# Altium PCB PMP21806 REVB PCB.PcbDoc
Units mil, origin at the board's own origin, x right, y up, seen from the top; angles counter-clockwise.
Board outline 1250 x 2200 mil, 2 copper layers (Top Layer, Bottom Layer), stack 62 mil thick; 54 components, 26 nets, 111 pads, 101 vias.
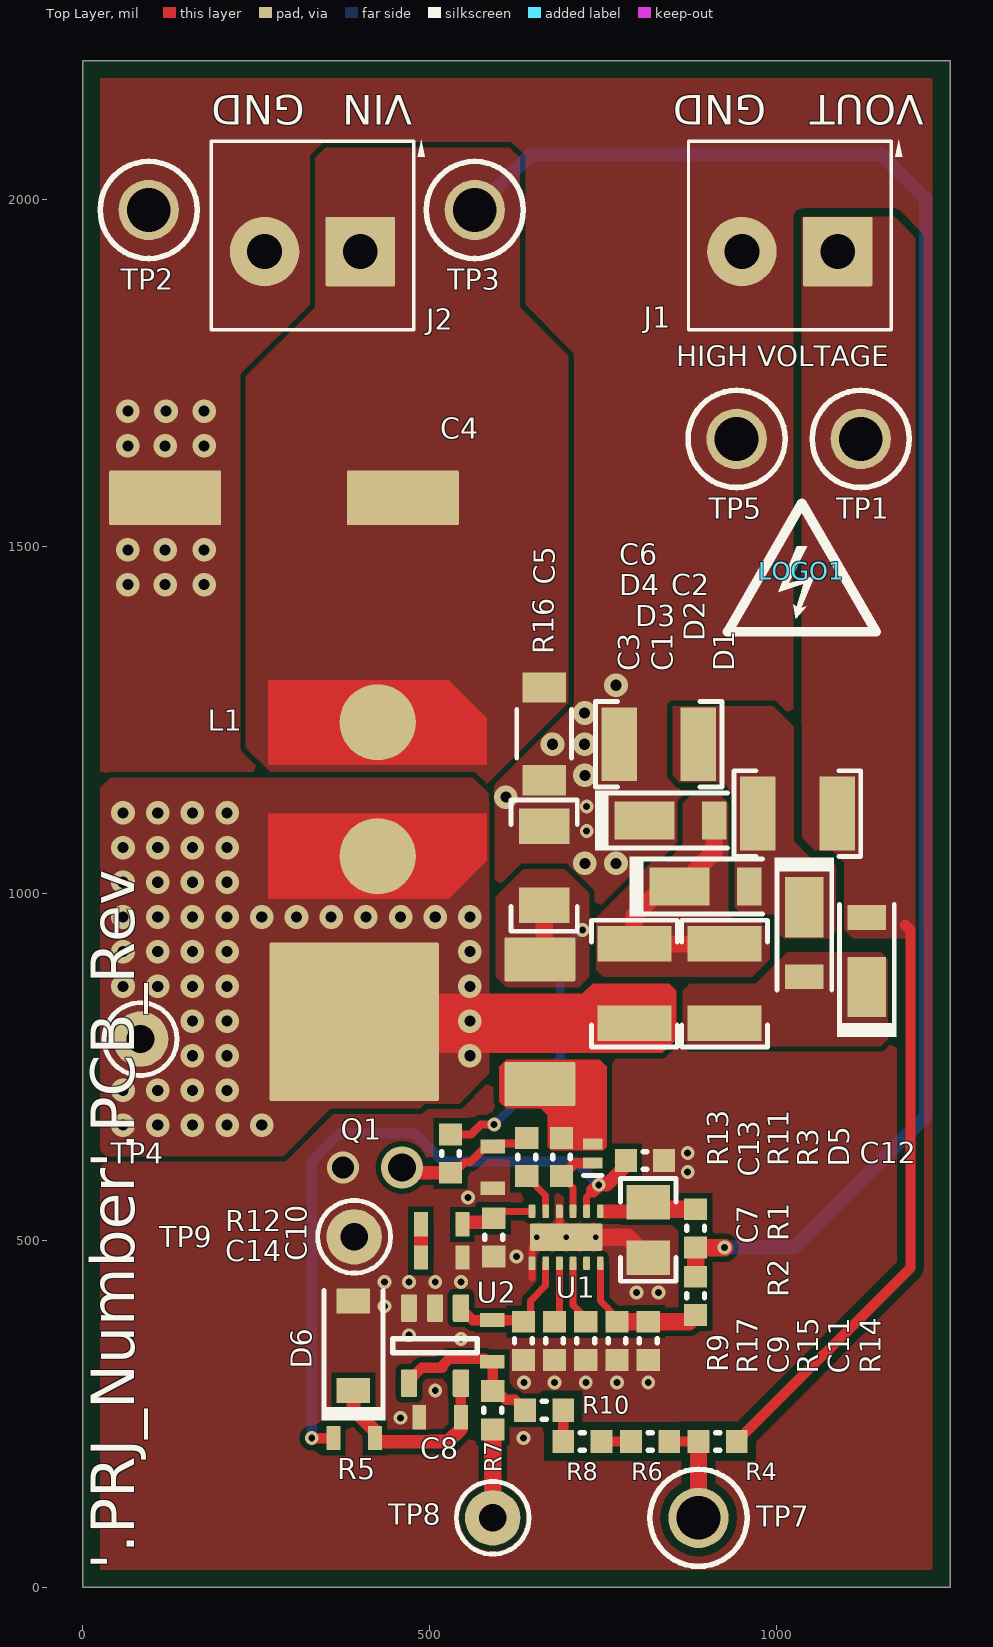
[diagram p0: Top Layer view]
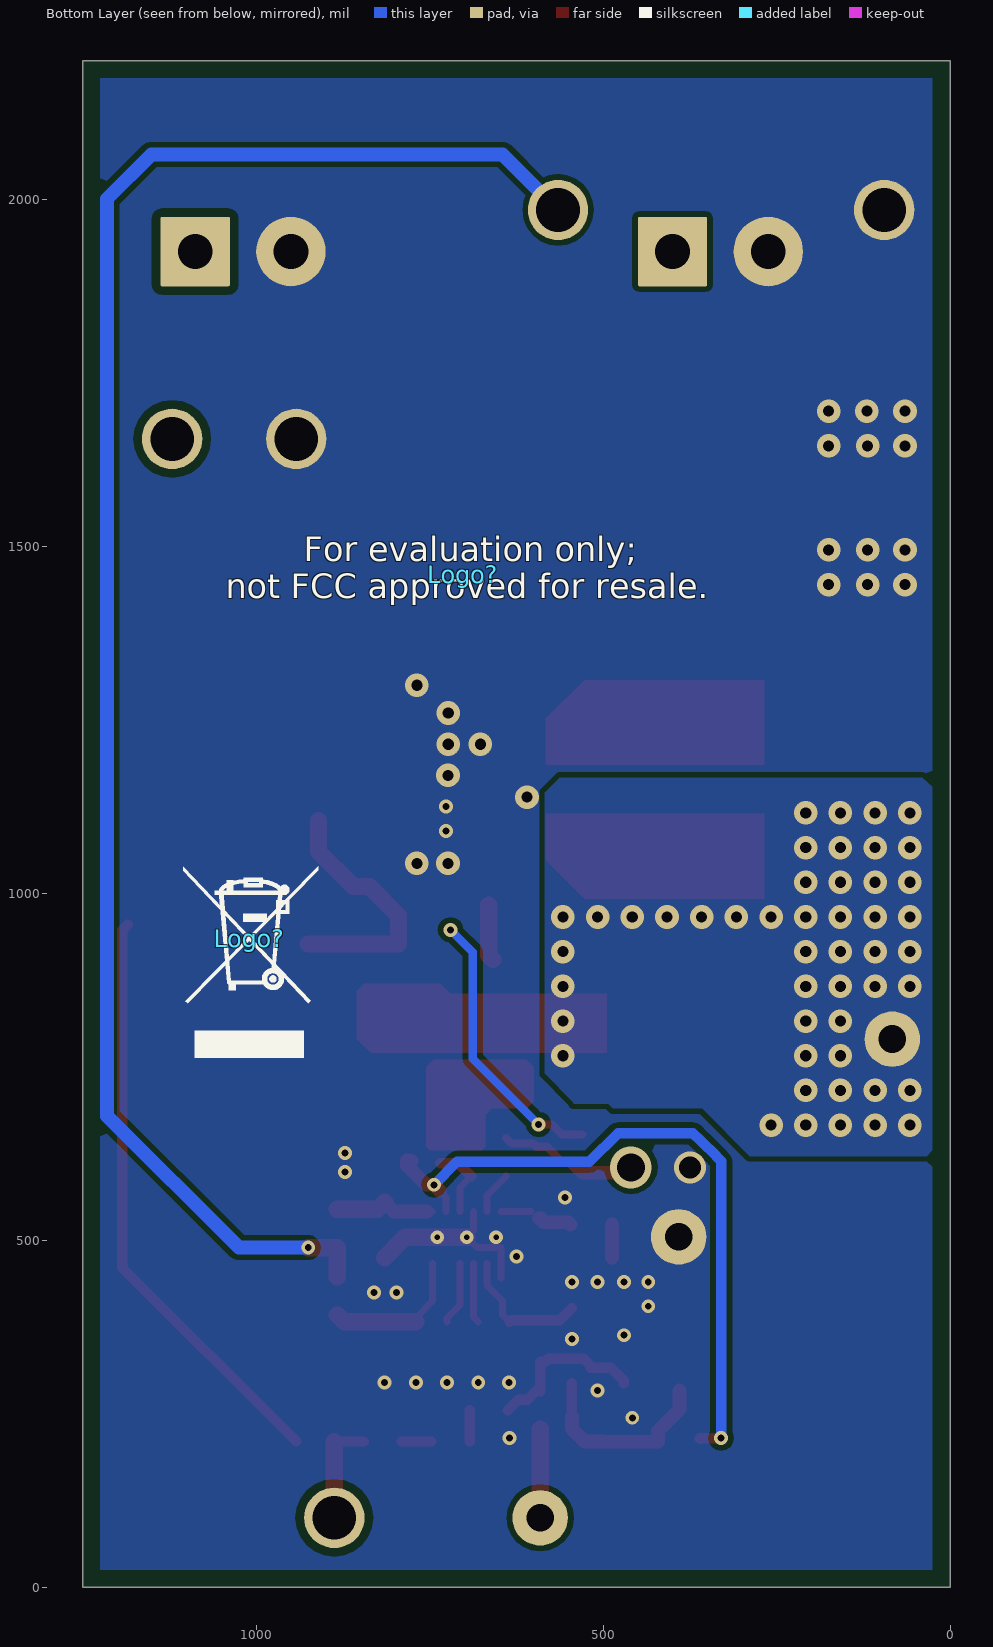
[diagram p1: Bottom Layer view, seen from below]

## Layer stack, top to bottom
Top Solder: solder mask 0.4, Solder Resist, Dk 3.5
Top Layer: signal copper 1.4
Dielectric1: core 59.2, FR-4, Dk 4.8
Bottom Layer: signal copper 1.4
Bottom Solder: solder mask 0.4, Solder Resist, Dk 3.5

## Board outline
0,0 1250,0 1250,2200 0,2200

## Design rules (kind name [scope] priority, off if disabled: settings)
AcuteAngle [All] p1: minimum=4.50000000000000E+0001 checktracksonly=FALSE
AssemblyTestPointUsage [All] p1: valid=2
BoardOutlineClearance BoardOutlineClearance_MountingHoles [OnCopper and InComponentClass('Mounting Holes')] p1: gap=25 ignorepadtopadclearanceinfootprint=FALSE
BoardOutlineClearance BoardOutlineClearance_Poly [OnCopper and InPoly] p2: gap=25 ignorepadtopadclearanceinfootprint=FALSE
BoardOutlineClearance [OnCopper and Not InComponentClass('Logo') and not InComponentClass('FiducialMark') and not InRegion(1000,500,4000,800)] p3: gap=25 ignorepadtopadclearanceinfootprint=FALSE
Clearance Clearance_HV [InNet('Vout') OR InNet('NetR4_2') OR InNet('NetR6_1') OR InNet('NetR8_1')] p1: gap=12 ignorepadtopadclearanceinfootprint=FALSE
Clearance Clearance_Keepouts [((IsTrack Or IsArc) And Not InPoly) And IsFree and IsKeepOut vs ((IsTrack Or IsArc) And Not InPoly) And IsFree and IsKeepOut] p2: gap=0 ignorepadtopadclearanceinfootprint=FALSE
Clearance Clearance_Poly [InPolygon] p3: gap=8 ignorepadtopadclearanceinfootprint=FALSE except(0: Arc-Hole Track-Hole SMDPad-Hole THPad-Hole Via-Hole Fill-Hole Poly-Hole Region-Hole Text-Hole)
Clearance [All] p4: gap=7.87 ignorepadtopadclearanceinfootprint=FALSE except(0: Arc-Hole Track-Hole SMDPad-Hole THPad-Hole Via-Hole Fill-Hole Poly-Hole Region-Hole Text-Hole)
ComponentClearance ComponentClearance_MountingHoles_FiducialMarks [InComponentClass('Mounting Holes') vs InComponentClass('FiducialMark')] p1: gap=50 collisioncheckmode=3 verticalgap=10 showdistances=FALSE
ComponentClearance ComponentClearance_Shunt [InComponentClass('Header') vs InComponentClass('Shunt')] p2: gap=0 collisioncheckmode=3 verticalgap=0 showdistances=FALSE
ComponentClearance ComponentClearance_Logo [InComponentClass('Logo')] p3: gap=50 collisioncheckmode=3 verticalgap=10 showdistances=FALSE
ComponentClearance ComponentClearance_ScrewToNut [(HasFootprint('NY PMS 440 0025 PH')) vs (HasFootprint('Keystone_1902C'))] p4: gap=5 collisioncheckmode=3 verticalgap=10 showdistances=FALSE
ComponentClearance ComponentClearance_MountingHoles [InComponentClass('Mounting Holes')] p5: gap=250 collisioncheckmode=3 verticalgap=100000 showdistances=FALSE
ComponentClearance ComponentClearance_SmallPassives [HasFootprint('0201*') or HasFootprint('0402*') or HasFootprint('0508') or HasFootprint('0603*') or HasFootprint('0612') or HasFootprint('0805*') or HasFootprint('0815*') or HasFootprint('0830*') or HasFootprint('1206*') or HasFootprint('1210*') or HasFootprint('1808*') or HasFootprint('1812*') or HasFootprint('1825*') or HasFootprint('2010*') or HasFootprint('2220*') or HasFootprint('2225*') or HasFootprint('2512*') or HasFootprint('2728*') or HasFootprint('3518*') vs HasFootprint('0201*') or HasFootprint('0402*') or HasFootprint('0508') or HasFootprint('0603*') or HasFootprint('0612') or HasFootprint('0805*') or HasFootprint('0815*') or HasFootprint('0830*') or HasFootprint('1206*') or HasFootprint('1210*') or HasFootprint('1808*') or HasFootprint('1812*') or HasFootprint('1825*') or HasFootprint('2010*') or HasFootprint('2220*') or HasFootprint('2225*') or HasFootprint('2512*') or HasFootprint('2728*') or HasFootprint('3518*')] p6: gap=5 collisioncheckmode=3 verticalgap=10 showdistances=FALSE
ComponentClearance ComponentClearance_THtoSMT [IsThruComponent vs IsSMTComponent] p7: gap=15 collisioncheckmode=3 verticalgap=30 showdistances=FALSE
ComponentClearance ComponentClearance_THtoTH [IsThruComponent vs IsThruComponent] p8: gap=15 collisioncheckmode=3 verticalgap=30 showdistances=FALSE
ComponentClearance [All] p9: gap=5 collisioncheckmode=3 verticalgap=10 showdistances=FALSE
DiffPairsRouting [All] p1: maxlimit=100 minlimit=10 mostfreqgap=10 toplayer_minwidth=15 toplayer_maxwidth=15 toplayer_prefwidth=15 bottomlayer_minwidth=15 bottomlayer_maxwidth=15 bottomlayer_prefwidth=15 maxuncoupledlength=1000
FabricationTestPointUsage TestPointUsage [All] p1: valid=2 allowmultiple=FALSE
FabricationTestpoint Testpoint [All] p1: side=3 testpointundercomponent=TRUE minsize=40 maxsize=100 preferedsize=60 minholesize=0 maxholesize=40 preferedholesize=32 testpointgrid=1 allowsidetop=TRUE allowsidebottom=TRUE usegrid=TRUE gridtolerance=0.01
FanoutControl Fanout_LCC [IsLCC] p1: bgadir=Out bgaviamode=Centered fanoutstyle=Auto fanoutdirection=Alternating viagrid=1 // Fanout_LCC (Default Rule)
FanoutControl Fanout_BGA [IsBGA] p2: bgadir=Out bgaviamode=Centered fanoutstyle=Auto fanoutdirection=Alternating viagrid=1 // Fanout_BGA (Default Rule)
FanoutControl Fanout_Default [All] p4: bgadir=Out bgaviamode=Centered fanoutstyle=Auto fanoutdirection=Alternating viagrid=1 // Fanout_Default (Default Rule)
FanoutControl Fanout_Small [(CompPinCount < 5)] p5: bgadir=Out bgaviamode=Centered fanoutstyle=Auto fanoutdirection=OutThenIn viagrid=1 // Fanout_Small (Default Rule)
HoleSize [All] p1: absolutevalues=TRUE maxlimit=251 minlimit=7.87 maxpercent=80.000 minpercent=20.000
MinimumAnnularRing MinimumAnnularRing_ThermalPadVias [IsVia and InAnyComponent] p1: minimumring=4
MinimumAnnularRing [All] p2: minimumring=4
MinimumSolderMaskSliver MinimumSolderMaskSliver_Logo [InComponentClass('Logo') vs InComponentClass('Logo')] p1: minsoldermaskwidth=0.7
MinimumSolderMaskSliver [All] p2: minsoldermaskwidth=2
PlaneClearance [All] p1: clearance=15
PlaneConnect [All] p1: planeconnectstyle=Direct reliefexpansion=10 reliefentries=4 reliefconductorwidth=10 reliefairgap=10
PolygonConnect [All] p1: connectstyle=Direct reliefconductorwidth=10 reliefentries=4 polygonreliefangle="90 Angle" airgapwidth=10
RoutingVias ThermalPadVias [IsVia and InAnyComponent] p1: holewidth=7.87 width=19.68 viastyle="Through Hole" minholewidth=7.87 minwidth=19.68 maxholewidth=12.99 maxwidth=23.62
RoutingVias [All] p2: holewidth=10 width=20 viastyle="Through Hole" minholewidth=6 minwidth=10 maxholewidth=40 maxwidth=65
SilkToBoardRegionClearance [Not ((IsComment or IsDesignator) And (Hide <> 'False')) and not InRegion(1000,500,4000,800)] p1:
SilkToSilkClearance SilkToSilkClearance_Pb-FreeLogo [(HasFootprint('Pb-Free_Overlay_Medium') OR HasFootprint('Pb-Free_Overlay_Small')) vs (HasFootprint('Pb-Free_Overlay_Medium') OR HasFootprint('Pb-Free_Overlay_Small'))] p1: silktosilkclearance=0
SilkToSilkClearance [All] p2: silktosilkclearance=0
SilkToSolderMaskClearance SilkToComponentPadClearance [IsPad and InAnycomponent] p1: minsilkscreentomaskgap=0 clearancetoexposedcopper=TRUE
SilkToSolderMaskClearance "Silk to Solder Mask Opening" [All] p2: minsilkscreentomaskgap=0 clearancetoexposedcopper=FALSE
SolderMaskExpansion [All] p1: expansion=1.97
Width [All] p1: maxlimit=100 minlimit=6 preferedwidth=10 checkconnectedcopper=TRUE
14 further rules are at their usual default settings.

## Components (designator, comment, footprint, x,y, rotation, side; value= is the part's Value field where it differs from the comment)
C1 "GRM32DR72E104KW01L" 1210_220 925,870 r270 top value=0.1uF
C2 "GRM32DR72E104KW01L" 1210_220 1030,1115 r180 top value=0.1uF
C3 "GRM32DR72E104KW01L" 1210_220 795,870 r90 top value=0.1uF
C4 "EEHZS1H221P" FP-EEHZS1H221P_RADIAL_SMD-MFG 290,1570 r0 top
C5 "CGA5L3X7R1H475K160AE" 1206_190 665,1230 r270 top value=4.7uF
C6 "GRM32DR72E104KW01L" 1210_220 830,1215 r180 top value=0.1uF
C7 "CGA4J3X7R1H105K125AB" 0805_HV 815,515 r270 top value=1uF
C8 "CGJ3E2X7R1C104K080AA" 0603S 514.9,245 r180 top value=0.1uF
C9 "CGA3E2X7R1H104K080AA" 0603L 680,355 r270 top value=0.1uF
C10 "GRM1885C1H100JA01D" 0603L 592.46,504.31 r270 top value=10pF
C11 "GRM1885C1H100JA01D" 0603L 770,355 r270 top value=10pF
C12 "GCM188R71C105KA64J" 0603L 810.31,615 r180 top value=1uF
C13 "GRM188R71H272KA01D" 0603S 590.83,605 r270 top value=2700pF
C14 "UMK107AB7105KA-T" 0603S 517.21,475.22 r0 top value=1uF
D1 "DFLU1200-7" PowerDI123 1130,915 r90 top value=200V
D2 "DFLU1200-7" PowerDI123 1040,929.8 r270 top value=200V
D3 "DFLU1200-7" PowerDI123 910.2,1010 r0 top value=200V
D4 "DFLU1200-7" PowerDI123 860,1105 r0 top value=200V
D5 "BAT54LP-7" X1-DFN1006-2 735,625 r90 top value=30V
D6 "MMSZ4688T1G" SOD-123 390,348.11 r90 top value=4.7V
J1 "ED555/2DS" TERM_BLK_ED555-2DS 1088,1925 r180 top
J2 "ED555/2DS" TERM_BLK_ED555-2DS 400,1925 r180 top
L1 "SRT8045-402ME" FP-SRT8045-402ME_SMT_IND_8MM0_8MM4-MFG 425,1150 r270 top
LOGO1 "DANGER HIGH VOLTAGE" IEC_HighVoltage_Small 1036.3,1465 r0 top
Logo? "WEEE logo" WEEE_Minimum 1010,935 r180 bottom
Logo? "FCC disclaimer" FCC_disclaimer_stacked 702.1,1460 r180 bottom
Q1 "IPD5N25S3430ATMA1" DPAK 525,815 r180 top value=250V
R1 "CRCW060310R0FKEA" 0603L 883.29,517.21 r270 top value=10.0
R2 "CRCW060360K4FKEA" 0603L 883.29,420 r90 top value=60.4k
R3 "CRCW060310R0FKEA" 0603L 690,620 r270 top value=10.0
R4 "CRCW060349R9FKEA" 0603L 915,210.12 r180 top value=49.9
R5 "CRCW06031K00FKEA" 0603S 391.14,215 r180 top value=1.00k
R6 "CRCW0603511KFKEA" 0603L 817.68,210 r0 top value=511k
R7 "CRCW060318K2FKEA" 0603L 590.83,255 r90 top value=18.2k
R8 "CRCW0603511KFKEA" 0603L 720,210 r0 top value=511k
R9 "CRCW060322K6FKEA" 0603S 590,355 r270 top value=22.6k
R10 "CRCW0603511KFKEA" 0603L 665,255 r0 top value=511k
R11 "CRCW06030000Z0EA" 0603L 640,620 r270 top value=0
R12 "ERA-3AEB101V" 0603S 517.25,523.01 r0 top value=100
R13 "CRCW0603100RFKEA" 0603L 530,625 r90 top value=100
R14 "CRCW060320K0FKEA" 0603L 815,355 r90 top value=20.0k
R15 "CRCW060388K7FKEA" 0603L 725,355 r90 top value=88.7k
R16 "CSR1206FK20L0" 1206 665,1040 r270 top value=0.02
R17 "CRCW06036K49FKEA" 0603L 635,355 r90 top value=6.49k
TP1 "5010" Keystone5010 1121.2,1655 r0 top
TP2 "5011" Keystone5011 95,1985 r180 top
TP3 "5010" Keystone5010 565,1985 r180 top
TP4 "5000" Keystone5000 83.31,790 r180 top
TP5 "5011" Keystone5011 942.33,1655 r180 top
TP7 "5013" Keystone5013 887.44,100 r180 top
TP8 "5000" Keystone5000 590.83,100 r180 top
TP9 "5001" Keystone5001 391.14,505 r180 top
U1 "LM5155QDSSTQ1" DSS0012C 696.7,504.31 r270 top
U2 "TLV314QDBVRQ1" DBV0005A_N 507.6,348.11 r270 top

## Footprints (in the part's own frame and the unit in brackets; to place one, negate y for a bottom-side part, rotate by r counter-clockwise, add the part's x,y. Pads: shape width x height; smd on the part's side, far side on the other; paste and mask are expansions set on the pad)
0603L [mm] "0603 from SM-752 data"
  rect 0.8x0.85 smd: 1(-0.7,0) 2(0.7,0)
  silkscreen extent -0.07,-0.33 0.07,0.33, body extent -0.87,-0.47 0.87,0.47, height 1
0603S [mil]
  rect 20x35 smd: 1(-30,0) 2(30,0)
  body extent -34,-19 34,19, height 39
0805_HV [mil] "0805 with 30mil clearance between pads"
  rect 50x63 smd: 1(-40,0) 2(40,0)
  silkscreen extent -74,-40 74,40, body extent -43,-29 43,29, height 57
1206 [mm] "1206 from SM-752 data"
  rect 1.3x1.85 smd: 1(-1.45,0) 2(1.45,0)
  silkscreen extent -2.4,-1.21 2.4,1.21, body extent -1.7,-0.9 1.7,0.9, height 1.35
1206_190 [mm] "1206_190"
  rect 1.1x1.6 smd: 1(-1.7,0) 2(1.7,0)
  silkscreen extent -0.9,-1 0.9,1, body extent -1.75,-0.95 1.75,0.95, height 1.9
1210_220 [mm] "1210"
  rect 1.3x2.7 smd: 1(-1.45,0) 2(1.45,0)
  silkscreen extent -2.32,-1.57 2.32,1.57, body extent -1.7,-1.35 1.7,1.35, height 2.2
DBV0005A_N [mm] "SOT23, 5-Leads, Body 2.9x1.6mm, Pitch 0.95mm, Lead Span 2.8mm, IPC Medium Density"
  rrect17% 1x0.6 smd: 1(-1.375,0.95) 2(-1.375,0) 3(-1.375,-0.95) 4(1.375,-0.95) 5(1.375,0.95)
  silkscreen extent -0.25,-1.55 0.25,1.55, body extent -1.42,-1.46 1.42,1.46, height 1.09
DPAK [mm] "D-PAK, 3-Pads, Body 6.22x6.73mm (max), TO-252AA using nominal STEP model"
  rrect6% 2.6x1.6 smd: 1(-3.4,2.28) 3(-3.4,-2.28)
  rrect2% 6.2x5.8 smd paste-3: 2(3.4,0)
  body extent -3.86,-3.29 5.84,3.29, height 2.48
DSS0012C [mm] "WSON-12"
  rrect40% 0.5x0.25 smd: 1(-0.95,1.25) 2(-0.95,0.75) 3(-0.95,0.25) 4(-0.95,-0.25) 5(-0.95,-0.75) 6(-0.95,-1.25) 7(0.95,-1.25) 8(0.95,-0.75) 9(0.95,-0.25) 10(0.95,0.25) 11(0.95,0.75) 12(0.95,1.25)
  rrect11% 0.95x1.17 on Top Paste: 13(0,0.685) 13(0,-0.685)
  rrect11% 1x2.65 smd paste-0.5: 13(0,0)
  body extent -1,-1.5 1,1.5, height 0.81
FCC_disclaimer_stacked [mil]
FP-EEHZS1H221P_RADIAL_SMD-MFG [mm]
  rrect5% 4.1x2 smd paste+0 mask+0: 1(-4.35,0) 2(4.35,0)
  body extent -6.65,-5.5 6.65,5.5, height 0.25
FP-SRT8045-402ME_SMT_IND_8MM0_8MM4-MFG [mm]
  round 2.79 smd paste+0 mask+0: 1(-2.45,0) 2(2.45,0)
  Top Layer region: 0.9,4 0.9,-4 4,-4 4,2.6 2.6,4
  Top Layer region: -0.9,4 -0.9,-4 -4,-4 -4,2.6 -2.6,4
  body extent -4.25,-4.45 4.25,4.45, height 0.25
IEC_HighVoltage_Small [mil]
  silkscreen extent -107,-88 107,97
Keystone5000 [mil] "For Keystone 500x miniature loop terminals"
  round 80 hole 40: 1(0,0)
  silkscreen extent -52,-52 52,52, body extent -49,-49 49,49, height 182
Keystone5001 [mil] "For Keystone 500x miniature loop terminals"
  round 80 hole 40: 1(0,0)
  silkscreen extent -52,-52 52,52, body extent -49,-49 49,49, height 182
Keystone5010 [mil] "Keystone Multipurpose loops"
  round 87 hole 63: 1(0,0)
  silkscreen extent -70,-70 70,70, body extent -63,-63 63,62, height 319
Keystone5011 [mil] "Keystone Multipurpose loops"
  round 87 hole 63: 1(0,0)
  silkscreen extent -70,-70 70,70, body extent -63,-63 63,62, height 319
Keystone5013 [mil] "Keystone Multipurpose loops"
  round 87 hole 63: 1(0,0)
  silkscreen extent -70,-70 70,70, body extent -63,-63 63,62, height 319
PowerDI123 [mm] "Diodes Inc recommended land pattern, document number DS30628 Rev. 6-2"
  rect 2.2x1.4 smd: 1(-1.275,0)
  rect 0.9x1.4 smd: 2(1.275,0)
  silkscreen extent -3.1,-1.09 1.76,1.09, body extent -2.38,-0.97 1.52,0.96, height 1
SOD-123 [mm] "On Semi recommended land pattern"
  rect 0.915x1.22 smd: 1(-1.637,0) 2(1.637,0)
  silkscreen extent -2.74,-1.17 2.03,1.17, body extent -1.93,-0.9 1.93,0.9, height 1.35
TERM_BLK_ED555-2DS [mil]
  rrect4% 100x100 hole 50: 1(0,0)
  round 100 hole 50: 2(138,0)
  silkscreen extent -93,-161 215,113, body extent -69,-150 207,106, height 323
WEEE_Minimum [mil] "WEEElie bin"
  silkscreen extent -95,-172 99,104
X1-DFN1006-2 [mm] "DIODES, INC"
  rect 0.4x0.7 smd: 1(-0.35,0) 2(0.35,0)
  silkscreen extent -0.8,-0.35 -0.8,0.35, body extent -0.54,-0.34 0.54,0.34, height 0.53

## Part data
C1 C2 C3 C6: library part CMP-0009192-2, "CAP, CERM, 0.1 uF, 250 V, +/- 10%, X7R, 1210", Cap_Case=1210, Manufacturer=MuRata, Supplier Part Number 1=490-3541-1-ND, TempCo=X7R, Tolerance_%=10%, Value1=Unknown, Value2=250V, ValueDisplayed=0.1uF
C4: library part CMP-0087071-1, "220µF 50V Aluminum Polymer Capacitor Radial, Can - SMD 13 mOhm 4000 Hrs @ 125°C", Manufacturer="Panasonic Electronic Components", Tolerance_%=20%
C5: library part CMP-0085349-1, "CAP, CERM, 4.7 µF, 50 V,+/- 10%, X7R, AEC-Q200 Grade 1, 1206", Cap_Case=1206, Manufacturer=TDK, TempCo=X7R, Tolerance_%=10%, Value2=50V, ValueDisplayed=4.7µF
C7: library part CMP-0007976-2, "CAP, CERM, 1 uF, 50 V, +/- 10%, X7R, AEC-Q200 Grade 1, 0805", Cap_Case=0805, Manufacturer=TDK, Supplier Part Number 1=445-6961-1-ND, TempCo=X7R, Tolerance_%=10%, Value1="0.008782 ohm", Value2=50V, ValueDisplayed=1uF
C8: library part CMP-0007106-4, "CAP, CERM, 0.1 uF, 16 V, +/- 10%, X7R, AEC-Q200 Grade 1, 0603", Cap_Case=0603, Manufacturer=TDK, Supplier Part Number 1=445-8136-1-ND, TempCo=X7R, Tolerance_%=10%, Value1=Unknown, Value2=16V, ValueDisplayed=0.1uF
C9: library part CMP-0007078-4, "CAP, CERM, 0.1 uF, 50 V, +/- 10%, X7R, AEC-Q200 Grade 1, 0603", Cap_Case=0603, Manufacturer=TDK, Supplier Part Number 1=445-5666-1-ND, TempCo=X7R, Tolerance_%=10%, Value1="0.0296 ohm", Value2=50V, ValueDisplayed=0.1uF
C10 C11: library part CMP-0007170-4, "CAP, CERM, 10 pF, 50 V, +/- 5%, C0G/NP0, 0603", Cap_Case=0603, Manufacturer=MuRata, Supplier Part Number 1=490-1403-1-ND, TempCo=C0G/NP0, Tolerance_%=5%, Value1=Unknown, Value2=50V, ValueDisplayed=10pF
C12: library part CMP-0079154-1, "CAP, CERM, 1 µF, 16 V,+/- 10%, X7R, AEC-Q200 Grade 1, 0603", Cap_Case=0603, Manufacturer=MuRata, Supplier Part Number 1=490-12657-1-ND, TempCo=X7R, Tolerance_%=10%, Value2=16V, ValueDisplayed=1µF
C13: library part CMP-0007447-4, "CAP, CERM, 2700 pF, 50 V, +/- 10%, X7R, 0603", Cap_Case=0603, Manufacturer=MuRata, Supplier Part Number 1=490-1502-1-ND, TempCo=X7R, Tolerance_%=10%, Value1=Unknown, Value2=50V, ValueDisplayed=2700pF
C14: library part CMP-0007508-5, "CAP, CERM, 1 uF, 50 V, +/- 10%, X7R, 0603", Cap_Case=0603, Manufacturer="Taiyo Yuden", Supplier Part Number 1=587-3247-1-ND, TempCo=X7R, Tolerance_%=10%, Value1=Unknown, Value2=50V, ValueDisplayed=1uF
D1 D2 D3 D4: library part CMP-0077072-2, "Diode, Superfast Rectifier, 200 V, 1 A, AEC-Q101, PowerDI123", Manufacturer="Diodes Inc.", Value1=1A, Value2=0.98V
D5: library part CMP-0076931-2, "Diode, Schottky, 30 V, 0.2 A, 1.00x0.50x0.60mm", Manufacturer="Diodes Inc.", Value1=0.2A, Value2=1V
D6: library part CMP-0005785-3, "Diode, Zener, 4.7 V, 500 mW, SOD-123", Manufacturer="ON Semiconductor", Power_W=500mW, Value1=0.5W
J1 J2: library part CMP-0074913-1, "Terminal Block, 3.5mm Pitch, 2x1, TH", Color=Grey, Current_A=6A, Manufacturer="On-Shore Technology", Supplier Part Number 1=ED1514-ND, Voltage_V=150V
L1: library part CMP-0086514-1, "Shielded Power Inductor 4uH 14.5mOhm 9.9A Surface Mount", Manufacturer=Coilcraft
LOGO1: library part CMP-0074835-1, "IEC 61010-1 High Voltage Warning"
Logo?: library part CMP-0074769-1
Logo?: library part CMP-0074847-1, "FCC_disclaimer"
Q1: library part CMP-0082696-2, "MOSFET, N-CH, 250 V, 5 A, AEC-Q101, DPAK", Alternate Manufacturer=None, Manufacturer="Infineon Technologies", Supplier Part Number 1=IPD5N25S3430ATMA1-ND, Value1="? ohm", Value2="4.7 nC"
R1 R3: library part CMP-0022003-4, "RES, 10.0, 1%, 0.1 W, AEC-Q200 Grade 0, 0603", Manufacturer=Vishay-Dale, Power_W=100mW, Supplier Part Number 1=541-10.0HCT-ND, TempCo="100 ppm/C", Tolerance_%=1%, Value2=0.1W, Value_Code=10R0, ValueDisplayed=10.0
R2: library part CMP-0022532-4, "RES, 60.4 k, 1%, 0.1 W, AEC-Q200 Grade 0, 0603", Manufacturer=Vishay-Dale, Power_W=100mW, Supplier Part Number 1=541-60.4KHCT-ND, TempCo="100 ppm/C", Tolerance_%=1%, Value2=0.1W, Value_Code=60k4, ValueDisplayed=60.4k
R4: library part CMP-0022448-4, "RES, 49.9, 1%, 0.1 W, AEC-Q200 Grade 0, 0603", Manufacturer=Vishay-Dale, Power_W=100mW, Supplier Part Number 1=541-49.9HCT-ND, TempCo="100 ppm/C", Tolerance_%=1%, Value2=0.1W, Value_Code=49R9, ValueDisplayed=49.9
R5: library part CMP-0022109-5, "RES, 1.00 k, 1%, 0.1 W, AEC-Q200 Grade 0, 0603", Manufacturer=Vishay-Dale, Power_W=100mW, Supplier Part Number 1=541-1.00KHCT-ND, TempCo="100 ppm/C", Tolerance_%=1%, Value2=0.1W, Value_Code=1k00, ValueDisplayed=1.00k
R6 R8 R10: library part CMP-0022480-4, "RES, 511 k, 1%, 0.1 W, AEC-Q200 Grade 0, 0603", Manufacturer=Vishay-Dale, Power_W=100mW, Supplier Part Number 1=541-511KHCT-ND, TempCo="100 ppm/C", Tolerance_%=1%, Value2=0.1W, Value_Code=511k
R7: library part CMP-0022097-4, "RES, 18.2 k, 1%, 0.1 W, AEC-Q200 Grade 0, 0603", Manufacturer=Vishay-Dale, Power_W=100mW, Supplier Part Number 1=541-18.2KHCT-ND, TempCo="100 ppm/C", Tolerance_%=1%, Value2=0.1W, Value_Code=18k2, ValueDisplayed=18.2k
R9: library part CMP-0022221-4, "RES, 22.6 k, 1%, 0.1 W, AEC-Q200 Grade 0, 0603", Manufacturer=Vishay-Dale, Power_W=100mW, Supplier Part Number 1=541-22.6KHCT-ND, TempCo="100 ppm/C", Tolerance_%=1%, Value2=0.1W, Value_Code=22k6, ValueDisplayed=22.6k
R11: library part CMP-0025697-4, "RES, 0, 5%, 0.1 W, AEC-Q200 Grade 0, 0603", Manufacturer=Vishay-Dale, Power_W=100mW, Supplier Part Number 1=541-0.0GCT-ND, TempCo="200 ppm/C", Tolerance_%=5%, Value2=0.1W, Value_Code=0000, ValueDisplayed=0
R12: library part CMP-0023361-3, "RES, 100, 0.1%, 0.1 W, AEC-Q200 Grade 0, 0603", Manufacturer=Panasonic, Power_W=100mW, Supplier Part Number 1=P100DBCT-ND, TempCo="25 ppm/C", Tolerance_%=0.1%, Value2=0.1W, Value_Code=100R, ValueDisplayed=100
R13: library part CMP-0021991-4, "RES, 100, 1%, 0.1 W, AEC-Q200 Grade 0, 0603", Manufacturer=Vishay-Dale, Power_W=100mW, Supplier Part Number 1=541-100HCT-ND, TempCo="100 ppm/C", Tolerance_%=1%, Value2=0.1W, Value_Code=100R, ValueDisplayed=100
R14: library part CMP-0022204-4, "RES, 20.0 k, 1%, 0.1 W, AEC-Q200 Grade 0, 0603", Manufacturer=Vishay-Dale, Power_W=100mW, Supplier Part Number 1=541-20.0KHCT-ND, TempCo="100 ppm/C", Tolerance_%=1%, Value2=0.1W, Value_Code=20k0, ValueDisplayed=20.0k
R15: library part CMP-0022632-4, "RES, 88.7 k, 1%, 0.1 W, AEC-Q200 Grade 0, 0603", Manufacturer=Vishay-Dale, Power_W=100mW, Supplier Part Number 1=541-88.7KHCT-ND, TempCo="100 ppm/C", Tolerance_%=1%, Value2=0.1W, Value_Code=88k7, ValueDisplayed=88.7k
R16: library part CMP-0017260-2, "RES, 0.02, 1%, 0.5 W, 1206", Manufacturer="Stackpole Electronics Inc", Power_W=500mW, Supplier Part Number 1=CSR1206FK20L0CT-ND, TempCo="100 ppm/C", Tolerance_%=1%, Value2=0.5W, Value_Code=R020, ValueDisplayed=0.02
R17: library part CMP-0022561-4, "RES, 6.49 k, 1%, 0.1 W, AEC-Q200 Grade 0, 0603", Manufacturer=Vishay-Dale, Power_W=100mW, Supplier Part Number 1=541-6.49KHCT-ND, TempCo="100 ppm/C", Tolerance_%=1%, Value2=0.1W, Value_Code=6k49, ValueDisplayed=6.49k
TP1 TP3: library part CMP-0055147-1, "Test Point, Multipurpose, Red, TH", Color=Red, Manufacturer=Keystone, Supplier Part Number 1=36-5010-ND
TP2 TP5: library part CMP-0055148-1, "Test Point, Multipurpose, Black, TH", Color=Black, Manufacturer=Keystone, Supplier Part Number 1=36-5011-ND
TP4 TP8: library part CMP-0055137-1, "Test Point, Miniature, Red, TH", Color=Red, Manufacturer=Keystone, Supplier Part Number 1=36-5000-ND
TP7: library part CMP-0055150-1, "Test Point, Multipurpose, Orange, TH", Color=Orange, Manufacturer=Keystone, Supplier Part Number 1=36-5013-ND
TP9: library part CMP-0055138-1, "Test Point, Miniature, Black, TH", Color=Black, Manufacturer=Keystone, Supplier Part Number 1=36-5001-ND
U1: library part CMP-0081538-1, "Automotive Grade 2.2-MHz Wide Input Non-synchronous Boost Controller, DSS0012C (WSON-12)", Alternate Manufacturer="Texas Instruments", Alternate PartNumber=LM5155QDSSRQ1
U2: library part CMP-0073534-1, "3-MHz, Low-Power, Internal EMI Filter, RRIO, Operational Amplifier, DBV0005A (SOT-23-5)", Alternate Manufacturer="Texas Instruments", Alternate PartNumber=TLV314QDBVTQ1

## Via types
v1: diameter 34, hole 16, Top Layer to Bottom Layer, 68 vias
v2: diameter 20, hole 10, Top Layer to Bottom Layer, tented both sides, 28 vias
v3: diameter 19.68, hole 7.87, Top Layer to Bottom Layer, 3 vias
v4: diameter 46, hole 32, Top Layer to Bottom Layer, 1 vias
v5: diameter 60, hole 40, Top Layer to Bottom Layer, 1 vias

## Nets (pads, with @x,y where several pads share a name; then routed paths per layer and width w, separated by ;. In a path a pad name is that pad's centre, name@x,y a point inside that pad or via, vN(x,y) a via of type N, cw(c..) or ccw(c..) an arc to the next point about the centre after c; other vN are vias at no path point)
GND: C4.1 C5.2 C6.2 C7.2 C8.2 C9.2 C10.2 C11.2 C12.1 C13.2 C14.2 D4.1 D6.2 J1.2 J2.2 R14.1 R15.1 R16.1 R17.1 TP2.1 TP5.1 TP9.1 U1.4 U1.7 U1.13@696.7,504.31 U2.2 U2.3 | length 271.1
  Top Layer w10: 647.49,445.73 U1.7 647.49,489.63 682.02,489.63 v3(696.7,504.31) 686.86,514.15 U1.4
  Top Layer w25: v3(696.7,504.31) v3(739.02,504.31) 785.69,504.31 C7.2
  other v1: 723.67,1043.16 768.54,1043.16 609.76,1138.75 723.67,1170 677.01,1215 723.27,1215 723.27,1260 768.54,1300 65,1445 118.74,1445 175,1445 65,1495 118.74,1495 175,1495 65,1645 118.74,1645 175,1645 65,1695 120,1695 175,1695
  other v2: 635,215 458,244.17 508,283.64 635.68,295 680,295 725,295 770,295 815,295 545,357.95 469.92,363.25 435,405 798,425 830,425 435,440 470,440 508,440 545,440 625,476.75 555,561.69 871.85,598.35 871.85,625.83 726.28,1090 726.28,1125
  other v3: 654.38,504.31
  other v4: 375,605
NetC1_1: C1.1 C3.2 D3.1 D4.2 | length 369.1
  Top Layer w25: D4.2 910.2,1060.2 D3.1 837.09,1010 795,967.91 C3.2 C1.1
NetC1_2: C1.2 D1.1 D2.2
NetC2_2: C2.2 C6.1 D2.1 D3.2
NetC3_1: C3.1 L1.2 Q1.2 TP4.1
  other v1: 58,666 108,666 158,666 208,666 258,666 58,716 108,716 158,716 208,716 158,766 208,766 558,766 158,816 208,816 558,816 58,866 108,866 158,866 208,866 558,866 58,916 108,916 158,916 208,916 558,916 58,966 108,966 158,966 208,966 258,966 308,966 358,966 408,966 458,966 508,966 558,966 58,1016 108,1016 158,1016 208,1016 58,1066 108,1066 158,1066 208,1066 58,1116 108,1116 158,1116 208,1116
NetC4_2: C4.2 C5.1 J2.1 L1.1 R1.2 R2.2 TP3.1 | length 2483.9
  Top Layer w25: R2.2 R1.2 883.53,489.41 v2(925,489.41)
  Bottom Layer w20: TP3.1 645,2065 1151.16,2065 1215,2001.16 1215,679.41 1025,489.41 v2(925,489.41)
NetC7_1: C7.1 R1.1 U1.1 | length 147.1
  Top Layer w10: U1.1 753.8,541.71
  Top Layer w20: 753.8,541.71 801.72,541.71 C7.1
  Top Layer w25: C7.1 825.23,544.77 R1.1
NetC8_1: C8.1 D6.1 R5.1 U2.5 | length 284.3
  Top Layer w15: C8.1@545,245.1 U2.5
  Top Layer w20: D6.1 390,256.46 421.14,225.31 R5.1 421.14,209.63 502.31,209.63 502.68,210 526.63,210 545,228.37 545,245.1 C8.1
NetC9_1: C9.1 U1.9 | length 87.2
  Top Layer w10: C9.1 686.86,389.42 U1.9
NetC10_1: C10.1 R12.2 U1.6 | length 93
  Top Layer w10: C10.1@604.27,541.71 U1.6
  Top Layer w20: R12.2 550.2,525.97 585,525.97 589.38,530.35 589.38,531.87 C10.1
NetC11_1: C11.1 R2.1 R14.2 U1.12 | length 211.7
  Top Layer w10: U1.12 745.91,412.33 770,388.25 C11.1
  Top Layer w25: C11.1 R14.2 873.4,382.56 R2.1
NetC12_2: C12.2 R5.2 U1.2 | length 1004.7
  Top Layer w10: U1.2 726.23,562.59 735.6,571.96
  Top Layer w15: v2(330,215) 358.86,215 360,213.86 R5.2
  Top Layer w20: 735.6,571.96 v2(743.64,580) 754.69,580 C12.2@782.75,608.07 ; C12.2@776.34,614.48 C12.2@782.75,608.07 ; C12.2 C12.2@782.75,608.07
  Bottom Layer w15: v2(330,215) 330,613.7 336.63,620.33 336.63,620.89 359.11,643.37 359.67,643.37 370.75,654.45 478.37,654.45 519.89,612.93 710.71,612.93 v2(743.64,580)
NetC13_1: C13.1 R11.1 R13.1 | length 203.9
  Top Layer w12: R13.1 535.28,597.44 550.77,612.93 559.07,612.93 581.14,635 C13.1 596.22,635 600.65,639.43 631.87,639.43 R11.1
  Top Layer w20: v5(460,605) 467.56,597.44 R13.1
NetC14_1: C14.1 R12.1 | length 47.8
  Top Layer w20: C14.1 487.25,475.27 R12.1
NetD5_1: D5.1 R3.2 U1.3 | length 110.4
  Top Layer w10: R3.2 706.54,575.9 U1.3
  Top Layer w15: R3.2 708.78,611.22 D5.1
NetD5_2: D5.2 Q1.1 R3.1 | length 48.6
  Top Layer w10: R3.1 726.22,647.56 D5.2
NetQ1_3: Q1.3 R13.2 R16.2 | length 483
  Top Layer w12: R13.2 559.3,652.56 573.77,667.02 v2(592.98,667.02)
  Top Layer w25: Q1.3 665,910.91 R16.2
  Bottom Layer w12: v2(592.98,667.02) 605.95,680 606.44,680 688.13,761.69 688.13,915.61 v2(720,947.48)
NetR4_2: R4.2 R6.2 TP7.1 | length 152.4
  Top Layer w15: R6.2 887.32,210 R4.2
  Top Layer w25: TP7.1 R4.2
NetR6_1: R6.1 R8.2 | length 42.6
  Top Layer w15: R8.2 R6.1
NetR7_1: R7.1 TP8.1 | length 127.6
  Top Layer w25: R7.1 TP8.1 TP8.1@590.94,99.88
NetR7_2: R7.2 R9.2 R10.1 U2.4 | length 240.5
  Top Layer w15: U2.4 470.2,297.95 488.73,316.48 517.82,316.48 517.82,318.85 528,329.04 579.43,329.04 583.46,325 R9.2 590.83,324.17 R7.2 596.97,282.56 609.53,270 622.44,270 R10.1
NetR8_1: R8.1 R10.2 | length 45
  Top Layer w15: R8.1 692.56,210.12 R10.2
NetR9_1: R9.1 R17.2 U1.8 U2.1 | length 195.8
  Top Layer w10: R17.2 645,392.56 645,412.48 667.17,434.65 U1.8
  Top Layer w15: U2.1 562.24,385 R9.1 632.56,385 R17.2
NetR11_2: R11.2 U1.5 | length 62
  Top Layer w10: R11.2 640,591.75 667.17,564.58 U1.5
NetR15_2: R15.2 U1.10 | length 92
  Top Layer w10: U1.10 706.54,406.7 725,388.25 R15.2
Vout: C2.1 D1.2 J1.1 R4.1 TP1.1 | length 851.9
  Top Layer w15: R4.1 1193,460.56 1193,947 1185,955
pads on no net: U1.11 U1.13@669.73,504.31 U1.13@723.67,504.31

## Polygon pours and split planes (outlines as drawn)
NetC3_1 on Top Layer "TOP_LAYER_NETC3_1_P043" (solid, remove dead copper, pour order 43): 562.24,1166.88 584.12,1145 585.95,1145 585.95,740.42 542.41,696.88 492.91,696.88 486.05,690.02 357.49,690.02 288.65,621.19 33.81,621.19 0,655 0,1126.88 40,1166.88
NetC3_1 on Top Layer "TOP_LAYER_NETC3_1_P053" (solid, remove dead copper, pour order 53): 95,775
Vout on Top Layer "TOP_LAYER_VOUT_P048" (solid, remove dead copper, pour order 48): 1110,935 1199.99,935 1200,935.01 1200,1945 1170,1975 1036.3,1975 1036.3,1081 1055.45,1061.85 1080,1061.85 1097.23,1044.62 1097.23,947.77
no net on Top Layer "TOP_LAYER_NONET_P052" (solid, remove dead copper, pour order 52): 920,1500
Vout on Top Layer "TOP_LAYER_VOUT_P051" (solid, remove dead copper, pour order 51): 1215,973.07
GND on Top Layer "TOP_LAYER_GND_P049" (solid, remove dead copper, pour order 49): 0,0 0,2200 1250,2200 1250,0
NetQ1_3 on Top Layer "TOP_LAYER_NETQ1_3_P035" (solid, remove dead copper, pour order 35): 635,1035 595,995 595,880 610,865 715,865 730,880 730,1000 695,1035
NetC4_2 on Top Layer "TOP_LAYER_NETC4_2_P047" (solid, remove dead copper, pour order 47): 310,1135 235,1210 235,1745 335,1845 335,2060 350,2075 615,2075 630,2060 630,1845 700,1775 700,1275 560,1135
NetC1_1 on Top Layer "TOP_LAYER_NETC1_1_P041" (solid, remove dead copper, pour order 41): 740,890 750,880 965,880 990,905 990,944.99 975,960 940,960 930,970 930,1130 920,1140 875,1140 865,1130 865,1070 840,1045 820,1045 740,965
NetC2_2 on Top Layer "TOP_LAYER_NETC2_2_P039" (solid, remove dead copper, pour order 39): 850,1270 850,1170 860,1160 925,1160 940,1135 940,980 950,970 995,970 1005,960 1005,940 1010,935 1075,935 1085,945 1085,1040 1075,1050 1050,1050 1025,1075 1025,1240 995,1270
NetC1_2 on Top Layer "TOP_LAYER_NETC1_2_P037" (solid, remove dead copper, pour order 37): 875,870 865,860 865,790 875,780 1150,780 1160,790 1160,905 1150,915 1015,915 970,870
NetC3_1 on Bottom Layer "BOTTOM_LAYER_NETC3_1_P045" (solid, remove dead copper, pour order 45): 40,1166.88 562.24,1166.88 584.27,1144.85 584.27,740.42 542.41,698.55 542.41,696.88 492.91,696.88 486.05,690.02 357.49,690.02 288.65,621.19 33.81,621.19 0,655 0,1130
GND on Bottom Layer "BOTTOM_LAYER_GND_P050" (solid, remove dead copper, pour order 50): 0,0 0,2200 1250,2200 1250,0

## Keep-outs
Keep-Out Layer:
  text ".Layer_Name" at 577,-858.49 h60

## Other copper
Top Layer:
  region net NetD5_2: 670,635 675,630 750,630 755,635 755,750 745,760 610,760 600,750 600,700 610,690 660,690 670,680
  region net NetC3_1: 845,870 855,860 855,790 835,770 495,770 495,855 720,855 735,870
  region: 800,865
  region: 20,1050
  region: 747.6,860
  region: 930,1105
  text ".Layer_Name" at 577,-858.49 h60
Bottom Layer:
  text ".Layer_Name" at 577,-858.49 h60

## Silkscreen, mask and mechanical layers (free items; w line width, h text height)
Top Overlay:
  text "GND" at 320,2165 h72.83 r180
  text "VIN" at 475,2165 h72.83 r180
  text "GND" at 985,2165 h72.83 r180
  text "VOUT" at 1212.24,2165 h72.83 r180
  text "HIGH VOLTAGE" at 855,1750 h50
  text "'.PRJ_Number'.PCB_Rev" at 95,25.49 h108.27 r90
  text ".Layer_Name" at 577,-858.49 h60
Bottom Overlay:
  text ".Layer_Name" at 577,-858.49 h60
Top Paste:
  text ".Layer_Name" at 577,-858.49 h60
Bottom Paste:
  text ".Layer_Name" at 577,-858.49 h60
Top Solder:
  text ".Layer_Name" at 577,-858.49 h60
  text ".Layer_Name" at 577,-858.49 h60
Bottom Solder:
  text ".Layer_Name" at 577,-858.49 h60
Drill Guide:
  text ".Layer_Name" at 577,-858.49 h60
M1 Board Outline:
  lines w10: 0,0 0,2200 ; 0,0 1250,0 ; 0,0 1250,0 ; 0,0 0,2200 ; 0,2200 1250,2200 ; 0,2200 1250,2200 ; 1250,0 1250,2200 ; 1250,0 1250,2200
  text ".Layer_Name" at 577,-858.49 h60
M2 Board Dimensions:
  rectangle: 0,-275 125,-150
  rectangle: 125,-400 500,-275
  lines w7: 0,-275 1000,-275 ; 125,-400 125,-150 ; 250,-400 250,-150 ; 500,-400 500,-150 ; 750,-400 750,-150 ; 0,-400 1000,-400 1000,-150 0,-150 0,-400
  text ".Layer_Name" at 577,-858.49 h60
M3 3D STEP Top:
  text ".Layer_Name" at 577,-858.49 h60
M4 3D STEP Bottom:
  text ".Layer_Name" at 577,-858.49 h60
M5 Assembly Top:
  lines w10: -292,-930.17 6308,-930.17 ; -292,-726.83 6310,-726.83 ; -292,-523.5 -292,-1133.5 3713,-1133.5 6310,-1133.5 6310,-523.5 -291.5,-523.5 -291.5,-1133.5 1284,-1133.5 ; 2173,-1133.5 2173,-523.5 ; 3440,-726.83 3440,-523.5 ; 4280,-726.83 4280,-523.5 ; 4902,-1140 4902,-937.17
  text "PMP21806B" at 105,35 h110 r90
  text "COMPONENTS MARKED 'DNP' SHOULD NOT BE POPULATED." at 1153.5,-318.5 h60
  text "ASSEMBLY VARIANT:" at 1153,-434 h60
  text ".VariantName" at 2189,-434 h60
  text "PCB VIEWED FROM TOP SIDE" at -228.5,-655.67 h60
  text "BOARD #:" at 2248,-655.67 h60
  text ".PRJ_Number" at 2793.5,-655.67 h60
  text "REV:" at 3638,-655.67 h60
  text ".PCB_Rev" at 3929.5,-655.67 h60
  text "SVN REV:" at 4476,-655.67 h60
  text ".VersionControl_RevNumber" at 4982,-655.67 h60
  text "TID #:" at 2248,-859 h60
  text ".TID" at 2793.5,-859 h60
  text "PLOT NAME =" at -228.5,-1064.34 h60
  text ".plot_File_Name" at 577,-1064.34 h60
  text "GENERATED    :" at 2250,-1064.34 h60
  text ".Print_Date" at 3119.5,-1064.34 h60
  text ".Print_Time" at 3848.5,-1064.34 h60
  text "TEXAS INSTRUMENTS" at 5113,-1064.34 h60
M6 Assembly Bottom:
  lines w10: -292.5,-727.33 6309.5,-727.33 ; -290.5,-930.67 6309.5,-930.67 ; 1115.5,-1140.5 1115.5,-937.67 ; 1737.5,-727.33 1737.5,-524 ; 2577.5,-727.33 2577.5,-524 ; 3844.5,-1134 3844.5,-524 ; 4733.5,-1134 6309,-1134 6309,-524 -292.5,-524 -292.5,-1134 2304.5,-1134 6309.5,-1134 6309.5,-524
  text "COMPONENTS MARKED 'DNP' SHOULD NOT BE POPULATED." at 6102,-318 h60
  text ".VariantName" at 5058,-434 h60
  text "ASSEMBLY VARIANT:" at 6097,-434 h60
  text ".VersionControl_RevNumber" at 1035.5,-656.17 h60
  text "SVN REV:" at 1541.5,-656.17 h60
  text ".PCB_Rev" at 2088,-656.17 h60
  text "REV:" at 2379.5,-656.17 h60
  text ".PRJ_Number" at 3224,-656.17 h60
  text "BOARD #:" at 3769.5,-656.17 h60
  text "PCB VIEWED FROM BOTTOM SIDE" at 6246,-656.17 h60
  text ".TID" at 3224,-859.5 h60
  text "TID #:" at 3769.5,-859.5 h60
  text "TEXAS INSTRUMENTS" at 904.5,-1064.84 h60
  text ".Print_Time" at 2169,-1064.84 h60
  text ".Print_Date" at 2898,-1064.84 h60
  text "GENERATED    :" at 3767.5,-1064.84 h60
  text ".plot_File_Name" at 5440.5,-1064.84 h60
  text "PLOT NAME =" at 6246,-1064.84 h60
M9 Title Sheet:
  drawing of 57 lines, arcs and shapes, not listed
  text "1" at 739.84,8036.5 h70
  text "2" at 3235.5,8036.5 h70
  text "3" at 5724.84,8036.5 h70
  text "4" at 8231.51,8036.5 h70
  text "5" at 10730.5,8036.5 h70
  text "6" at 13235.5,8036.5 h70
  text "A" at -416.5,6893.5 h70
  text "A" at 14383.5,6893.5 h70
  text "B" at -416.5,4513.5 h70
  text "B" at 14383.5,4513.5 h70
  text "C" at -416.5,2138.5 h70
  text "C" at 14383.5,2138.5 h70
  text "PROJECT TITLE:" at 11343.5,277.5 h45
  text ".PRJ_Title" at 11393.5,144.17 h70
  text "DESIGNED FOR:" at 11343.5,-23.5 h45
  text ".PRJ_Customer" at 11393.5,-163.5 h70
  text "D" at -416.5,-231.5 h70
  text "D" at 14383.5,-231.5 h70
  text "FILE NAME:" at 11343.5,-323.5 h45
  text ".PCB_File_Name_No_Path" at 11393.5,-443.5 h70
  text "Texas Instruments (TI) and/or its licensors do not warrant the accuracy or completeness of this specification" at 6374,-605.34 h45
  text "ENGINEER:" at 11343.5,-613.5 h45
  text "LAYOUT BY:" at 12848.5,-613.5 h45
  text "or any information contained therein. TI and/or its licensors do not warrant that this design will meet" at 6329.01,-718 h45
  text ".PRJ_Engineer" at 11393.5,-768.49 h70
  text ".PCB_Layout" at 12899,-768.49 h70
  text "the specifications, will be suitable for your application or fit for any particular purpose, or will operate in" at 6329.01,-830.67 h45
  text ".Layer_Name" at 577,-858.49 h60
  text "ALTIUM DESIGNER VERSION:" at 12848.5,-923.5 h45
  text "an implementation. TI and/or its licensors do not warrant that the design is production worthy. You should" at 6329.01,-943.33 h45
  text "completely validate and test your design implementation to confirm the system functionality for your application." at 6374,-1056 h45
  text ".print_Scale" at 11393.5,-1056.83 h70
  text ".Application_BuildNumber" at 12899,-1056.83 h70
  text "1" at 739.84,-1263.5 h70
  text "2" at 3235.5,-1263.5 h70
  text "3" at 5724.84,-1263.5 h70
  text "4" at 8231.51,-1263.5 h70
  text "5" at 10730.5,-1263.5 h70
  text "6" at 13235.5,-1263.5 h70
M10 Fab Notes:
  drawing of 189 lines, arcs and shapes, not listed
  text "DESIGN INFORMATION" at 12382.02,6356.17 h60
  text "MIN. TRACK WIDTH:" at 11737.46,6224.05 h60
  text "8" at 12833.7,6224.05 h60
  text "MIL" at 12988.46,6224.05 h60
  text "MIN. CLEARANCE:" at 11737.46,6099.92 h60
  text "0.2" at 12773.7,6099.93 h60
  text "mm" at 12988.46,6099.92 h60
  text "MIN. VIA PAD SIZE:" at 11737.46,5975.8 h60
  text "24" at 12803.71,5975.8 h60
  text "MIL" at 12988.46,5975.8 h60
  text "0.05mm (2MIL)" at 12432.46,5845.9 h60
  text "MINIMUM ANNULAR RING" at 11408.23,5837.67 h60
  text "EXTERNAL" at 13140.46,5837.67 h60
  text "PER" at 11608.23,5727.55 h60
  text "IPC-D-275 CLASS 2 LEVEL C" at 11828.23,5727.54 h60
  text "MIL, HOLES" at 13316.46,5627.07 h60
  text "+/-" at 12924,5618.48 h60
  text "+/-" at 13778,5618.48 h60
  text "REGISTRATION TOLERANCES:" at 11408.23,5617.42 h60
  text "METAL" at 12608,5617.42 h60
  text "5" at 13184.2,5617.42 h60
  text "3" at 14017.2,5617.42 h60
  text "MIL" at 14133.46,5617.42 h60
  text "HOLE SIZE TOLERANCE (UNLESS OTHERWISE SPECIFIED):" at 11408.23,5519.1 h60
  text "+/-" at 13778,5516.23 h60
  text "3" at 14017.2,5515.17 h60
  text "MIL" at 14133.46,5515.17 h60
  text "MATERIAL:" at 11333.46,5377.52 h60
  text "FR-4 High Tg" at 12319.9,5249 h60
  text "X" at 12175.46,5241.01 h60
  text "FR-408" at 11754.46,5236.49 h60
  text "OTHER" at 13242.46,5236.49 h60
  text "62 MIL (1.6mm) +/-10%" at 12074.56,5093.46 h60
  text "X" at 11954.46,5091.01 h60
  text "THICKNESS:" at 11408.23,5085.24 h60
  text "OTHER" at 13359.46,5085.24 h60
  text "TOLERANCE:" at 11408.23,4946.92 h60
  text "X" at 12256.46,4946.92 h60
  text "ANSI IPC-6012 TYPE 3 CLASS 2" at 12434.48,4946.92 h60
  text "OTHER +/-" at 12434.46,4802.73 h60
  text "BOW & TWIST:" at 11408.23,4657.54 h60
  text "X" at 12256.46,4657.54 h60
  text "ANSI IPC-6012 TYPE 3 CLASS 2" at 12434.48,4657.54 h60
  text "OTHER +/-" at 12434.46,4510.85 h60
  text "DRILLING:" at 11333.46,4380.23 h60
  text "NC_DRILL FILES" at 13094.46,4275.04 h60
  text "REFERENCE:" at 11408.23,4271.1 h60
  text "X" at 12065.46,4271.01 h60
  text "AS SHOWN" at 12243.46,4271.1 h60
  text "X" at 12966.46,4271.1 h60
  text "OTHER" at 13392.46,4128.85 h60
  text "PTH COPPER THICKNESS:" at 11407.91,4125.32 h60
  text "X" at 12547.14,4125.32 h60
  text "20-30 um" at 12675.14,4125.32 h60
  text "BOARD FINISH:" at 11333.46,3977.73 h60
  text "SILKSCREEN:" at 11488.68,3867.6 h60
  text "X" at 12446.46,3867.6 h60
  text "TOP" at 12563.46,3867.6 h60
  text "X" at 12956.46,3867.6 h60
  text "BOTTOM" at 13074.46,3867.6 h60
  text "SILKSCREEN COLOR:" at 11488.68,3712.41 h60
  text "X" at 12445.46,3712.41 h60
  text "WHITE" at 12563.46,3712.41 h60
  text "OTHER" at 13074.46,3712.41 h60
  text "X" at 12576.46,3568.96 h60
  text "GREEN" at 12694.46,3568.96 h60
  text "OTHER" at 13312.46,3568.96 h60
  text "SOLDER RESIST COLOR:" at 11488.68,3562.1 h60
  text "X" at 12576.46,3414.71 h60
  text "MATTE" at 12694.46,3414.71 h60
  text "SEMI-GLOSS" at 13312,3414.07 h60
  text "IMMERSION GOLD (ENIG)" at 12394.46,3241.94 h60
  text "ENEPIG" at 13732,3234.72 h60
  text "SURFACE FINISH:" at 11333.46,3233.72 h60
  text "X" at 12216.46,3233.72 h60
  text "IMM. TIN/SILVER OR EQUIV" at 11663,3096.4 h60
  text "OTHER" at 13094.46,3092.47 h60
  text "ARRAY/PANEL:" at 11333.46,2937.09 h60
  text "CUT AND TRIM PER M1 BOARD OUTLINE" at 12394.46,2928.87 h60
  text "N.C. ROUTE" at 12394.46,2792.9 h60
  text "X" at 13082.46,2792.9 h60
  text "V. SCORE" at 13260.46,2792.9 h60
  text "CERTIFICATION:" at 11333.46,2663.77 h60
  text "MATERIALS AND WORKMANSHIP FOR ALL PCBS" at 12058.46,2663.77 h60
  text "TO MEET OR EXCEED THE REQUIREMENTS OF:" at 12058.46,2569.71 h60
  text "X" at 11695.97,2441.08 h60
  text "ANSI IPC-A-600F CLASS ->" at 11823.96,2441.08 h60
  text "X" at 13471.97,2441.08 h60
  text "2" at 13581.96,2441.08 h60
  text "1" at 13266.96,2439.58 h60
  text "3" at 13935.96,2439.58 h60
  text "X" at 12507.97,2293.39 h60
  text "RoHS" at 12635.96,2293.39 h60
  text "OTHER" at 13280.36,2293.39 h60
  text "PER ORDER" at 13677.42,2293.39 h60
  text "ALL BOARDS MUST MEET OR EXCEED UL94-V0 REQUIREMENTS." at 11361,2139.57 h60
  text "PCB MUST BEAR THE UL94V-0 UL REGISTERED MATERIAL ID NUMBER" at 11361,2023.5 h60
  text "ADDITIONAL REQUIREMENTS:" at 11333.46,1854.08 h60
  text "MICROSECTION:" at 11408.23,1746.95 h60
  text "YES" at 12313.96,1746.95 h60
  text "REQUIRED" at 13175.46,1602.62 h60
  text "BARE BOARD ELEC. TEST:" at 11408.23,1599.76 h60
  text "NONE" at 12713.96,1599.76 h60
  text "X" at 13057.46,1599.76 h60
  text "PER ORDER" at 13767.46,1599.76 h60
  text "XX MIL VIAS REQUIRE NON-CONDUCTIVE FILL AND PLANARIZE" at 11576.38,1394.82 h59
  text "XX MIL VIAS REQUIRE CONDUCTIVE FILL AND PLANARIZE" at 11584.38,1290.84 h60
  text "OUTER XX MIL VIAS REQUIRE 50 OHM SINGLE-ENDED IMPEDANCE" at 11583.39,1127.46 h58
  text "LAYER 2 & 3 (INNER LAYERS) XX MIL WIDE, XX MIL SPACE / TRACES REQUIRE 100 OHM DIFFERENTIAL IMPEDANCE" at 11575.39,891.74 h60
  text ".Layer_Name" at 577,-858.49 h60
M11 Gerber Information:
  lines w10: -292,-930.17 6308,-930.17 ; -292,-726.83 6310,-726.83 ; -292,-523.5 -292,-1133.5 3713,-1133.5 6310,-1133.5 6310,-523.5 -291.5,-523.5 -291.5,-1133.5 1284,-1133.5 ; 2173,-1133.5 2173,-523.5 ; 3440,-726.83 3440,-523.5 ; 4280,-726.83 4280,-523.5 ; 4902,-1140 4902,-937.17
  text "ALL ARTWORK VIEWED FROM TOP SIDE" at -228.5,-655.67 h60
  text "BOARD #:" at 2248,-655.67 h60
  text ".PRJ_Number" at 2793.5,-655.67 h60
  text "REV:" at 3638,-655.67 h60
  text ".PCB_Rev" at 3929.5,-655.67 h60
  text "SVN REV:" at 4476,-655.67 h60
  text ".VersionControl_RevNumber" at 4982,-655.67 h60
  text "LAYER NAME =" at -228.5,-858.49 h60
  text "TID #:" at 2248,-859 h60
  text ".TID" at 2793.5,-859 h60
  text "PLOT NAME =" at -228.5,-1064.34 h60
  text ".plot_File_Name" at 577,-1064.34 h60
  text "GENERATED    :" at 2250,-1064.34 h60
  text ".Print_Date" at 3119.5,-1064.34 h60
  text ".Print_Time" at 3848.5,-1064.34 h60
  text "TEXAS INSTRUMENTS" at 5113,-1064.34 h60
M12 Stackup:
  drawing of 191 lines, arcs and shapes, not listed
  text "Layer" at 9645.34,7650 h60
  text "Name" at 10055.26,7650 h60
  text "Material" at 10985,7650 h60
  text "Thickness" at 11844.77,7650 h60
  text "Constant" at 12494.6,7650 h60
  text "Board Layer Stack" at 13064.46,7650 h60
  text "1" at 9645.34,7530 h60
  text "Top Overlay" at 10055.26,7530 h60
  text "2" at 9645.34,7410 h60
  text "Top Solder" at 10055.26,7410 h60
  text "Solder Resist" at 10985,7410 h60
  text "0.40mil" at 11844.77,7410 h60
  text "3.5" at 12494.6,7410 h60
  text "3" at 9645.34,7290 h60
  text "Top Layer" at 10055.26,7290 h60
  text "Copper" at 10985,7290 h60
  text "1.40mil" at 11844.77,7290 h60
  text "4" at 9645.34,7170 h60
  text "Dielectric1" at 10055.26,7170 h60
  text "FR-4" at 10985,7170 h60
  text "59.20mil" at 11844.77,7170 h60
  text "4.8" at 12494.6,7170 h60
  text "5" at 9645.34,7050 h60
  text "Bottom Layer" at 10055.26,7050 h60
  text "Copper" at 10985,7050 h60
  text "1.40mil" at 11844.77,7050 h60
  text "6" at 9645.34,6930 h60
  text "Bottom Solder" at 10055.26,6930 h60
  text "Solder Resist" at 10985,6930 h60
  text "0.40mil" at 11844.77,6930 h60
  text "3.5" at 12494.6,6930 h60
  text "7" at 9645.34,6810 h60
  text "Bottom Overlay" at 10055.26,6810 h60
  text ".Layer_Name" at 577,-858.49 h60
M13 Component Bodies Top:
  text ".Layer_Name" at 577,-858.49 h60
M14 Component Bodies Bottom:
  text ".Layer_Name" at 577,-858.49 h60
M15 Courtyards Top:
  text ".Layer_Name" at 577,-858.49 h60
M16 Courtyards Bottom:
  text ".Layer_Name" at 577,-858.49 h60
Drill Drawing:
  circle w10: c3053.72,2523.36 r27.63
  lines w10: 3026.09,2675.31 3081.34,2675.31 3053.72,2620.06 3026.09,2675.31 ; 3026.09,2744.38 3081.34,2744.38 3081.34,2799.63 3026.09,2799.63 3026.09,2744.38 ; 3026.09,2868.7 3026.09,2882.51 3039.9,2896.32 3026.09,2910.14 3026.09,2923.95 3039.9,2923.95 3053.72,2910.14 3067.53,2923.95 3081.34,2923.95 3081.34,2910.14 3067.53,2896.32 3081.34,2882.51 3081.34,2868.7 3067.53,2868.7 3053.72,2882.51 3039.9,2868.7 3026.09,2868.7 ; 3026.09,3020.64 3053.72,2993.02 3081.34,3020.64 3053.72,3048.27 3026.09,3020.64 ; 3026.09,3117.34 3053.72,3131.15 3081.34,3117.34 3067.53,3144.96 3081.34,3172.59 3053.72,3158.78 3026.09,3172.59 3039.9,3144.96 3026.09,3117.34 ; 3026.09,3255.47 3039.9,3255.47 3053.72,3241.66 3067.53,3255.47 3081.34,3255.47 3067.53,3269.28 3081.34,3283.1 3067.53,3283.1 3053.72,3296.91 3039.9,3283.1 3026.09,3283.1 3039.9,3269.28 3026.09,3255.47
  lines w12: 2976,2458.44 6207.49,2458.44 ; 2976,3328.68 6207.49,3328.68 ; 3313.86,2334.12 3313.86,3453 ; 3645.86,2334.12 3645.86,3453 ; 4282.43,2334.12 4282.43,3453 ; 4541.57,2334.12 4541.57,3453 ; 4916.72,2334.12 4916.72,3453 ; 5641.05,2334.12 5641.05,3453 ; 2976,2334.12 6207.49,2334.12 6207.49,3453 2976,3453 2976,2334.12
  text "Symbol" at 3050.59,3365.98 h72
  text "Quantity" at 3351.16,3365.98 h72
  text "Finished Hole Size" at 3683.16,3365.98 h72
  text "Plated" at 4319.72,3365.98 h72
  text "Hole Type" at 4578.86,3365.98 h72
  text "Drill Layer Pair" at 4954.02,3365.98 h72
  text "Hole Tolerance" at 5678.35,3365.98 h72
  text "3" at 3351.16,3241.66 h60
  text "7.87mil (0.200mm)" at 3683.16,3241.66 h60
  text "PTH" at 4319.72,3241.66 h60
  text "Round" at 4578.86,3241.66 h60
  text "Top Layer - Bottom Layer" at 4954.02,3241.66 h60
  text "28" at 3351.16,3117.34 h60
  text "10.00mil (0.254mm)" at 3683.16,3117.34 h60
  text "PTH" at 4319.72,3117.34 h60
  text "Round" at 4578.86,3117.34 h60
  text "Top Layer - Bottom Layer" at 4954.02,3117.34 h60
  text "68" at 3351.16,2993.02 h60
  text "16.00mil (0.406mm)" at 3683.16,2993.02 h60
  text "PTH" at 4319.72,2993.02 h60
  text "Round" at 4578.86,2993.02 h60
  text "Top Layer - Bottom Layer" at 4954.02,2993.02 h60
  text "1" at 3351.16,2868.7 h60
  text "32.00mil (0.813mm)" at 3683.16,2868.7 h60
  text "PTH" at 4319.72,2868.7 h60
  text "Round" at 4578.86,2868.7 h60
  text "Top Layer - Bottom Layer" at 4954.02,2868.7 h60
  text "4" at 3351.16,2744.38 h60
  text "40.00mil (1.016mm)" at 3683.16,2744.38 h60
  text "PTH" at 4319.72,2744.38 h60
  text "Round" at 4578.86,2744.38 h60
  text "Top Layer - Bottom Layer" at 4954.02,2744.38 h60
  text "4" at 3351.16,2620.06 h60
  text "50.00mil (1.270mm)" at 3683.16,2620.06 h60
  text "PTH" at 4319.72,2620.06 h60
  text "Round" at 4578.86,2620.06 h60
  text "Top Layer - Bottom Layer" at 4954.02,2620.06 h60
  text "5" at 3351.16,2495.74 h60
  text "63.00mil (1.600mm)" at 3683.16,2495.74 h60
  text "PTH" at 4319.72,2495.74 h60
  text "Round" at 4578.86,2495.74 h60
  text "Top Layer - Bottom Layer" at 4954.02,2495.74 h60
  text "113 Total" at 3351.16,2371.42 h60
  text ".Layer_Name" at 577,-858.49 h60
M17 Embedded Cavity:
  text ".Layer_Name" at 577,-858.49 h60
M18 Embedded Assembly:
  text ".Layer_Name" at 577,-858.49 h60
M19 Embedded Keepout:
  text ".Layer_Name" at 577,-858.49 h60

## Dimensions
0,-400 to 1000,-400 on M2 Board Dimensions
0,0 to 1250,2200 on M2 Board Dimensions
0,0 to 1250,2200 on M2 Board Dimensions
